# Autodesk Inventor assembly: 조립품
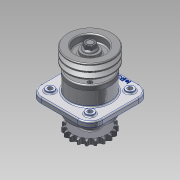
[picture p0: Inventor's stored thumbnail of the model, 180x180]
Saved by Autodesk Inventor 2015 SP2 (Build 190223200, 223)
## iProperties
Created: 2015-07
Part Number: 조립품
Document SubType Name: Assembly
Designer: AMC
Author: AMC
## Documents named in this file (12)
- C:\Users\AMC\Desktop\450735V1011\조립품.iam
- C:\Users\AMC\Desktop\450735V1011\본체.ipt
- C:\Users\AMC\Desktop\450735V1011\2-커버.ipt
- C:\Users\AMC\Desktop\450735V1011\3-축.ipt
- C:\Users\AMC\Desktop\450735V1011\4-V벨트풀리.ipt
- C:\Users\AMC\Desktop\450735V1011\5-체인 스프로킷.ipt
- C:\Users\AMC\Desktop\450735V1011\6-베어링 6206.ipt
- C:\Users\AMC\Desktop\450735V1011\7-부시.ipt
- C:\Users\AMC\Desktop\450735V1011\8-오일실 30x42.ipt
- C:\Users\AMC\Desktop\450735V1011\9-M16-너트.ipt
- C:\Users\AMC\Desktop\450735V1011\10-M6.ipt
- C:\Users\AMC\Desktop\450735V1011\11-키 6x6.ipt
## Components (22 placed, 10 different names)
1. 2-커버:1
2. 3-축:1
3. 4-V벨트풀리:1 — 각도:1
4. 5-체인 스프로킷:1 — 각도:2
5. 6-베어링 6206:1
6. 7-부시:1
7. 8-8-오일실 30x42:1
8. 9-M16 너트:1
9. 11-키 6x6:1 — 각도:1
10. 6-베어링 6206:2
11. 8-8-오일실 30x42:2
12. 2-커버:2
13. 9-M16 너트:2
14. 11-키 6x6:2 — 각도:2
15. 10-M6:2
16. 10-M6:1
17. 10-M6:3
18. 10-M6:4
19. 10-M6:5
20. 10-M6:6
21. 10-M6:7
22. 10-M6:8
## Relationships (2: Angle 2)
- 각도:1 [Angle]: 4-V벨트풀리:1 ↔ 11-키 6x6:1
- 각도:2 [Angle]: 5-체인 스프로킷:1 ↔ 11-키 6x6:2
